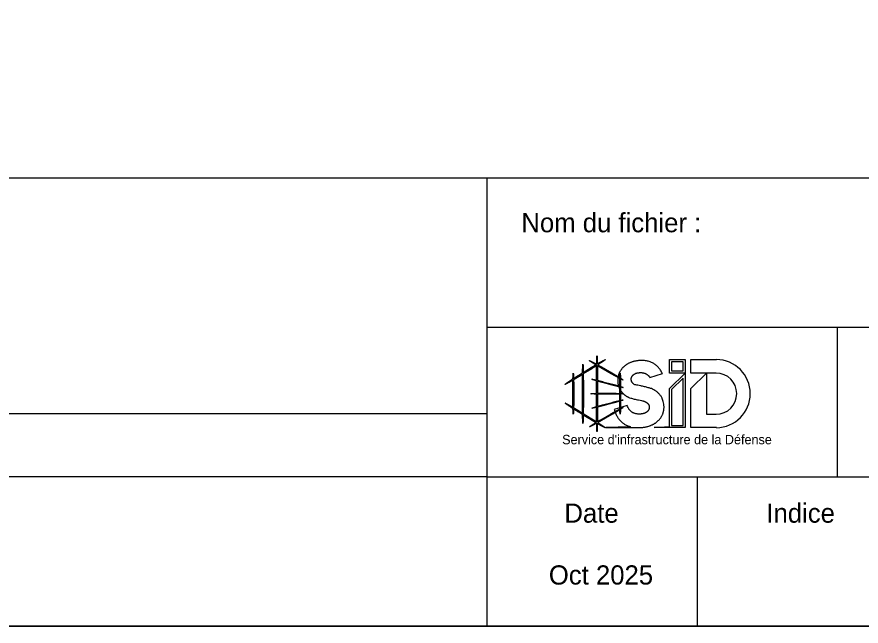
# Model space of a CAD drawing. Extents: x 37864 to 38032, y 453991 to 454052.
# Drawn here: x 37923.89 to 37937.08, y 453990.82 to 454000.33 of the extents above; entities that cross this region are included whole.
import ezdxf

# ---------------------------------------------------------------- set-up
doc = ezdxf.new("R2010")
doc.units = 0

msp = doc.modelspace()

# ---------------------------------------------------------------- linework, layer by layer
at = {"layer": 'DEFPOINTS'}
for p, q in [((37931.232, 453997.816), (37931.232, 453990.816)), ((37931.232, 453995.483), (37941.08, 453995.483)), ((37936.702, 453995.483), (37936.702, 453993.149)), ((37932.737, 453994.778), (37932.86, 453994.853)), ((37932.87, 453994.836), (37932.738, 453994.754)), ((37933.173, 453994.758), (37933.011, 453994.851)), ((37933.02, 453994.865), (37933.182, 453994.772)), ((37932.666, 453994.734), (37932.727, 453994.772)), ((37932.727, 453994.748), (37932.677, 453994.717)), ((37932.945, 453994.657), (37932.945, 453994.716)), ((37932.959, 453994.716), (37932.959, 453994.654)), ((37933.778, 453994.7), (37933.973, 453994.76)), ((37932.575, 453994.347), (37932.575, 453994.544)), ((37932.588, 453994.544), (37932.588, 453994.347)), ((37932.725, 453994.303), (37932.725, 453994.588)), ((37932.739, 453994.588), (37932.739, 453994.303)), ((37932.945, 453994.451), (37932.945, 453994.647)), ((37932.959, 453994.643), (37932.959, 453994.451)), ((37933.19, 453994.581), (37933.04, 453994.62)), ((37933.044, 453994.633), (37933.193, 453994.594)), ((37933.307, 453994.45), (37933.307, 453994.544)), ((37933.321, 453994.544), (37933.321, 453994.449)), ((37932.945, 453994.244), (37932.945, 453994.44)), ((37932.959, 453994.44), (37932.959, 453994.248)), ((37933.031, 453994.452), (37933.186, 453994.452)), ((37933.186, 453994.439), (37933.031, 453994.439)), ((37933.307, 453994.347), (37933.307, 453994.441)), ((37933.321, 453994.442), (37933.321, 453994.347)), ((37933.04, 453994.271), (37933.19, 453994.31)), ((37933.193, 453994.297), (37933.044, 453994.258)), ((37932.727, 453994.119), (37932.666, 453994.157)), ((37932.677, 453994.174), (37932.727, 453994.143)), ((37932.738, 453994.137), (37932.87, 453994.055)), ((37932.945, 453994.175), (37932.945, 453994.234)), ((37932.959, 453994.237), (37932.959, 453994.175)), ((37933.011, 453994.04), (37933.173, 453994.133)), ((37932.86, 453994.038), (37932.737, 453994.113)), ((37933.182, 453994.119), (37933.02, 453994.026)), ((37933.476, 453993.93), (37933.091, 453993.916)), ((37933.091, 453993.916), (37933.602, 453993.916)), ((37931.232, 453993.149), (37946.064, 453993.149)), ((37934.514, 453993.149), (37934.514, 453990.816))]:
    msp.add_line(p, q, dxfattribs=at)
for points in [[(37864.064, 453990.816), (37946.064, 453990.816), (37946.064, 454048.216), (37864.064, 454048.216)], [(37906.064, 453997.816), (37946.064, 453997.816), (37946.064, 453990.816), (37906.064, 453990.816)], [(37934.085, 453994.979), (37934.328, 453994.979), (37934.328, 453994.768), (37934.085, 453994.768)], [(37934.117, 453994.801), (37934.295, 453994.801), (37934.295, 453994.946), (37934.117, 453994.946)], [(37934.328, 453993.916), (37934.085, 453993.916), (37933.843, 453993.916), (37934.085, 453993.936), (37934.085, 453994.525), (37934.328, 453994.768)], [(37934.295, 453994.689), (37934.117, 453994.511), (37934.117, 453993.948), (37934.295, 453993.948)], [(37916.578, 453994.139), (37931.232, 453994.139), (37931.232, 453993.149), (37916.578, 453993.149)]]:
    msp.add_lwpolyline(points, close=True, dxfattribs=at)
for points in [[(37934.813, 453994.768), (37934.417, 453994.768), (37934.417, 453994.979), (37934.817, 453994.979)], [(37934.817, 453993.916), (37934.417, 453993.916), (37934.417, 453994.525), (37934.66, 453994.768), (37934.66, 453994.126), (37934.813, 453994.126)], [(37933.429, 453994.247), (37933.424, 453994.264), (37933.219, 453994.201)]]:
    msp.add_lwpolyline(points, dxfattribs=at)
for radius, start, end in [(0.532, 270.4248, 89.5752), (0.321, 270, 90)]:
    msp.add_arc((37934.813, 453994.447), radius, start, end, dxfattribs=at)
for points, degree in [([(37932.933, 453994.897), (37932.891, 453994.923), (37932.852, 453994.948), (37932.834, 453994.963)], 2), ([(37932.834, 453994.963), (37932.857, 453994.954), (37932.901, 453994.931), (37932.947, 453994.906)], 2), ([(37932.947, 453994.906), (37932.949, 453994.961), (37932.95, 453995.008), (37932.952, 453995.036)], 2), ([(37932.952, 453995.036), (37932.955, 453995.009), (37932.956, 453994.964), (37932.957, 453994.912)], 2), ([(37932.957, 453994.912), (37933.008, 453994.941), (37933.056, 453994.967), (37933.082, 453994.978)], 2), ([(37933.082, 453994.978), (37933.06, 453994.96), (37933.014, 453994.929), (37932.965, 453994.896)], 2), ([(37933.6, 453994.962), (37933.442, 453994.946), (37933.353, 453994.849)], 2), ([(37933.973, 453994.76), (37933.864, 453994.988), (37933.6, 453994.962)], 2), ([(37932.727, 453994.772), (37932.728, 453994.829), (37932.73, 453994.879), (37932.732, 453994.908)], 2), ([(37932.732, 453994.908), (37932.735, 453994.88), (37932.736, 453994.833), (37932.737, 453994.778)], 2), ([(37932.86, 453994.853), (37932.864, 453994.856), (37932.869, 453994.859), (37932.873, 453994.862)], 2), ([(37932.884, 453994.845), (37932.879, 453994.842), (37932.875, 453994.839), (37932.87, 453994.836)], 2), ([(37932.873, 453994.862), (37932.892, 453994.873), (37932.913, 453994.885), (37932.933, 453994.897)], 2), ([(37932.947, 453994.885), (37932.926, 453994.871), (37932.904, 453994.857), (37932.884, 453994.845)], 2), ([(37932.946, 453994.736), (37932.946, 453994.784), (37932.946, 453994.836), (37932.947, 453994.885)], 2), ([(37932.947, 453994.906), (37932.947, 453994.906), (37932.947, 453994.906), (37932.947, 453994.906)], 2), ([(37932.958, 453994.882), (37932.959, 453994.834), (37932.959, 453994.783), (37932.959, 453994.736)], 2), ([(37933, 453994.857), (37932.986, 453994.865), (37932.972, 453994.874), (37932.958, 453994.882)], 2), ([(37932.965, 453994.896), (37932.979, 453994.888), (37932.994, 453994.88), (37933.008, 453994.872)], 2), ([(37933.011, 453994.851), (37933.008, 453994.853), (37933.004, 453994.855), (37933, 453994.857)], 2), ([(37933.008, 453994.872), (37933.012, 453994.87), (37933.016, 453994.867), (37933.02, 453994.865)], 2), ([(37933.353, 453994.849), (37933.265, 453994.752), (37933.277, 453994.624)], 2), ([(37932.455, 453994.592), (37932.477, 453994.611), (37932.525, 453994.644), (37932.577, 453994.677)], 2), ([(37932.576, 453994.657), (37932.526, 453994.628), (37932.48, 453994.603), (37932.455, 453994.592)], 2), ([(37932.575, 453994.558), (37932.575, 453994.59), (37932.575, 453994.625), (37932.576, 453994.657)], 2), ([(37932.577, 453994.677), (37932.578, 453994.714), (37932.579, 453994.747), (37932.581, 453994.765)], 2), ([(37932.581, 453994.765), (37932.584, 453994.748), (37932.585, 453994.718), (37932.586, 453994.684)], 2), ([(37932.586, 453994.684), (37932.609, 453994.698), (37932.631, 453994.712), (37932.653, 453994.726)], 2), ([(37932.663, 453994.709), (37932.639, 453994.694), (37932.613, 453994.678), (37932.587, 453994.663)], 2), ([(37932.587, 453994.663), (37932.588, 453994.629), (37932.588, 453994.592), (37932.588, 453994.558)], 2), ([(37932.653, 453994.726), (37932.657, 453994.729), (37932.662, 453994.732), (37932.666, 453994.734)], 2), ([(37932.677, 453994.717), (37932.673, 453994.714), (37932.668, 453994.712), (37932.663, 453994.709)], 2), ([(37932.725, 453994.608), (37932.726, 453994.653), (37932.726, 453994.702), (37932.727, 453994.748)], 2), ([(37932.738, 453994.754), (37932.738, 453994.707), (37932.739, 453994.655), (37932.739, 453994.608)], 2), ([(37932.945, 453994.647), (37932.915, 453994.656), (37932.889, 453994.664), (37932.874, 453994.671)], 2), ([(37932.874, 453994.671), (37932.889, 453994.669), (37932.916, 453994.664), (37932.945, 453994.657)], 2), ([(37932.945, 453994.716), (37932.945, 453994.722), (37932.946, 453994.729), (37932.946, 453994.736)], 2), ([(37932.959, 453994.736), (37932.959, 453994.729), (37932.959, 453994.722), (37932.959, 453994.716)], 2), ([(37932.959, 453994.654), (37932.984, 453994.648), (37933.01, 453994.642), (37933.033, 453994.636)], 2), ([(37933.185, 453994.751), (37933.181, 453994.753), (37933.177, 453994.756), (37933.173, 453994.758)], 2), ([(37933.182, 453994.772), (37933.185, 453994.77), (37933.189, 453994.768), (37933.193, 453994.766)], 2), ([(37933.309, 453994.684), (37933.272, 453994.703), (37933.225, 453994.728), (37933.185, 453994.751)], 2), ([(37933.193, 453994.766), (37933.232, 453994.743), (37933.275, 453994.717), (37933.309, 453994.695)], 2), ([(37933.307, 453994.562), (37933.307, 453994.602), (37933.308, 453994.646), (37933.309, 453994.684)], 2), ([(37933.309, 453994.695), (37933.31, 453994.724), (37933.312, 453994.75), (37933.314, 453994.765)], 2), ([(37933.314, 453994.765), (37933.316, 453994.749), (37933.317, 453994.721), (37933.318, 453994.689)], 2), ([(37933.318, 453994.689), (37933.336, 453994.678), (37933.35, 453994.668), (37933.359, 453994.66)], 2), ([(37933.359, 453994.66), (37933.349, 453994.664), (37933.335, 453994.671), (37933.319, 453994.679)], 2), ([(37933.319, 453994.679), (37933.32, 453994.641), (37933.32, 453994.597), (37933.321, 453994.558)], 2), ([(37933.487, 453994.662), (37933.483, 453994.702), (37933.514, 453994.735)], 2), ([(37933.535, 453994.59), (37933.492, 453994.619), (37933.487, 453994.662)], 2), ([(37933.514, 453994.735), (37933.545, 453994.769), (37933.609, 453994.774)], 2), ([(37933.609, 453994.774), (37933.68, 453994.78), (37933.724, 453994.753)], 2), ([(37933.724, 453994.753), (37933.752, 453994.736), (37933.778, 453994.7)], 2), ([(37932.575, 453994.544), (37932.575, 453994.549), (37932.575, 453994.553), (37932.575, 453994.558)], 2), ([(37932.588, 453994.558), (37932.588, 453994.553), (37932.588, 453994.549), (37932.588, 453994.544)], 2), ([(37932.725, 453994.588), (37932.725, 453994.595), (37932.725, 453994.601), (37932.725, 453994.608)], 2), ([(37932.739, 453994.608), (37932.739, 453994.601), (37932.739, 453994.595), (37932.739, 453994.588)], 2), ([(37933.03, 453994.623), (37933.007, 453994.629), (37932.983, 453994.636), (37932.959, 453994.643)], 2), ([(37933.04, 453994.62), (37933.037, 453994.621), (37933.033, 453994.622), (37933.03, 453994.623)], 2), ([(37933.033, 453994.636), (37933.037, 453994.635), (37933.04, 453994.634), (37933.044, 453994.633)], 2), ([(37933.2, 453994.578), (37933.197, 453994.579), (37933.193, 453994.58), (37933.19, 453994.581)], 2), ([(37933.193, 453994.594), (37933.197, 453994.593), (37933.2, 453994.592), (37933.204, 453994.591)], 2), ([(37933.307, 453994.553), (37933.274, 453994.56), (37933.235, 453994.569), (37933.2, 453994.578)], 2), ([(37933.204, 453994.591), (37933.238, 453994.582), (37933.276, 453994.571), (37933.307, 453994.562)], 2), ([(37933.277, 453994.624), (37933.285, 453994.539), (37933.335, 453994.477)], 2), ([(37933.307, 453994.544), (37933.307, 453994.547), (37933.307, 453994.55), (37933.307, 453994.553)], 2), ([(37933.321, 453994.558), (37933.321, 453994.558), (37933.321, 453994.558), (37933.321, 453994.557)], 2), ([(37933.321, 453994.557), (37933.337, 453994.552), (37933.35, 453994.547), (37933.359, 453994.544)], 2), ([(37933.359, 453994.544), (37933.35, 453994.544), (37933.337, 453994.547), (37933.321, 453994.55)], 2), ([(37933.321, 453994.55), (37933.321, 453994.548), (37933.321, 453994.546), (37933.321, 453994.544)], 2), ([(37933.998, 453994.256), (37933.996, 453994.29), (37933.98, 453994.351), (37933.964, 453994.388), (37933.94, 453994.424), (37933.905, 453994.46), (37933.875, 453994.486), (37933.84, 453994.507), (37933.803, 453994.525), (37933.754, 453994.54), (37933.692, 453994.555), (37933.633, 453994.569), (37933.593, 453994.576), (37933.545, 453994.585), (37933.535, 453994.59)], 3), ([(37932.858, 453994.446), (37932.875, 453994.448), (37932.909, 453994.45), (37932.945, 453994.451)], 2), ([(37932.945, 453994.44), (37932.909, 453994.441), (37932.875, 453994.443), (37932.858, 453994.446)], 2), ([(37932.959, 453994.451), (37932.98, 453994.452), (37933.001, 453994.452), (37933.02, 453994.452)], 2), ([(37933.02, 453994.439), (37933.001, 453994.439), (37932.98, 453994.439), (37932.959, 453994.44)], 2), ([(37933.02, 453994.452), (37933.024, 453994.452), (37933.028, 453994.452), (37933.031, 453994.452)], 2), ([(37933.031, 453994.439), (37933.028, 453994.439), (37933.024, 453994.439), (37933.02, 453994.439)], 2), ([(37933.186, 453994.452), (37933.189, 453994.452), (37933.193, 453994.452), (37933.197, 453994.452)], 2), ([(37933.197, 453994.439), (37933.193, 453994.439), (37933.189, 453994.439), (37933.186, 453994.439)], 2), ([(37933.197, 453994.452), (37933.233, 453994.452), (37933.274, 453994.451), (37933.307, 453994.45)], 2), ([(37933.307, 453994.441), (37933.274, 453994.44), (37933.233, 453994.439), (37933.197, 453994.439)], 2), ([(37933.321, 453994.449), (37933.337, 453994.448), (37933.35, 453994.447), (37933.359, 453994.446)], 2), ([(37933.359, 453994.446), (37933.35, 453994.444), (37933.337, 453994.443), (37933.321, 453994.442)], 2), ([(37933.335, 453994.477), (37933.385, 453994.416), (37933.448, 453994.388)], 2), ([(37933.448, 453994.388), (37933.456, 453994.385), (37933.477, 453994.378), (37933.531, 453994.362), (37933.596, 453994.35), (37933.665, 453994.336), (37933.672, 453994.333)], 3), ([(37932.577, 453994.214), (37932.525, 453994.247), (37932.477, 453994.28), (37932.455, 453994.299)], 2), ([(37932.455, 453994.299), (37932.48, 453994.288), (37932.526, 453994.263), (37932.576, 453994.234)], 2), ([(37932.575, 453994.333), (37932.575, 453994.338), (37932.575, 453994.342), (37932.575, 453994.347)], 2), ([(37932.576, 453994.234), (37932.575, 453994.266), (37932.575, 453994.301), (37932.575, 453994.333)], 2), ([(37932.588, 453994.333), (37932.588, 453994.299), (37932.588, 453994.262), (37932.587, 453994.228)], 2), ([(37932.588, 453994.347), (37932.588, 453994.342), (37932.588, 453994.338), (37932.588, 453994.333)], 2), ([(37932.725, 453994.283), (37932.725, 453994.29), (37932.725, 453994.296), (37932.725, 453994.303)], 2), ([(37932.727, 453994.143), (37932.726, 453994.189), (37932.726, 453994.238), (37932.725, 453994.283)], 2), ([(37932.739, 453994.283), (37932.739, 453994.236), (37932.738, 453994.184), (37932.738, 453994.137)], 2), ([(37932.739, 453994.303), (37932.739, 453994.296), (37932.739, 453994.29), (37932.739, 453994.283)], 2), ([(37932.959, 453994.248), (37932.983, 453994.255), (37933.007, 453994.262), (37933.03, 453994.268)], 2), ([(37933.03, 453994.268), (37933.033, 453994.269), (37933.037, 453994.27), (37933.04, 453994.271)], 2), ([(37933.044, 453994.258), (37933.04, 453994.257), (37933.037, 453994.256), (37933.033, 453994.255)], 2), ([(37933.19, 453994.31), (37933.193, 453994.311), (37933.197, 453994.312), (37933.2, 453994.313)], 2), ([(37933.204, 453994.3), (37933.2, 453994.299), (37933.197, 453994.298), (37933.193, 453994.297)], 2), ([(37933.2, 453994.313), (37933.235, 453994.322), (37933.274, 453994.331), (37933.307, 453994.338)], 2), ([(37933.307, 453994.329), (37933.276, 453994.32), (37933.238, 453994.309), (37933.204, 453994.3)], 2), ([(37933.307, 453994.338), (37933.307, 453994.341), (37933.307, 453994.344), (37933.307, 453994.347)], 2), ([(37933.309, 453994.207), (37933.308, 453994.245), (37933.307, 453994.289), (37933.307, 453994.329)], 2), ([(37933.321, 453994.333), (37933.32, 453994.294), (37933.32, 453994.25), (37933.319, 453994.212)], 2), ([(37933.321, 453994.347), (37933.321, 453994.345), (37933.321, 453994.343), (37933.321, 453994.341)], 2), ([(37933.321, 453994.341), (37933.337, 453994.344), (37933.35, 453994.347), (37933.359, 453994.347)], 2), ([(37933.359, 453994.347), (37933.35, 453994.344), (37933.337, 453994.339), (37933.321, 453994.334)], 2), ([(37933.321, 453994.334), (37933.321, 453994.333), (37933.321, 453994.333), (37933.321, 453994.333)], 2), ([(37933.672, 453994.333), (37933.721, 453994.316), (37933.738, 453994.3)], 2), ([(37933.738, 453994.3), (37933.766, 453994.273), (37933.768, 453994.24)], 2), ([(37932.581, 453994.126), (37932.579, 453994.144), (37932.578, 453994.177), (37932.577, 453994.214)], 2), ([(37932.586, 453994.207), (37932.585, 453994.173), (37932.584, 453994.143), (37932.581, 453994.126)], 2), ([(37932.653, 453994.165), (37932.631, 453994.179), (37932.609, 453994.193), (37932.586, 453994.207)], 2), ([(37932.587, 453994.228), (37932.613, 453994.213), (37932.639, 453994.197), (37932.663, 453994.182)], 2), ([(37932.666, 453994.157), (37932.662, 453994.159), (37932.657, 453994.162), (37932.653, 453994.165)], 2), ([(37932.663, 453994.182), (37932.668, 453994.179), (37932.673, 453994.177), (37932.677, 453994.174)], 2), ([(37932.874, 453994.22), (37932.889, 453994.227), (37932.915, 453994.235), (37932.945, 453994.244)], 2), ([(37932.945, 453994.234), (37932.916, 453994.227), (37932.889, 453994.222), (37932.874, 453994.22)], 2), ([(37932.946, 453994.155), (37932.946, 453994.162), (37932.945, 453994.169), (37932.945, 453994.175)], 2), ([(37932.947, 453994.006), (37932.946, 453994.055), (37932.946, 453994.107), (37932.946, 453994.155)], 2), ([(37932.959, 453994.155), (37932.959, 453994.108), (37932.959, 453994.057), (37932.958, 453994.009)], 2), ([(37933.033, 453994.255), (37933.01, 453994.249), (37932.984, 453994.243), (37932.959, 453994.237)], 2), ([(37932.959, 453994.175), (37932.959, 453994.169), (37932.959, 453994.162), (37932.959, 453994.155)], 2), ([(37933.173, 453994.133), (37933.177, 453994.135), (37933.181, 453994.138), (37933.185, 453994.14)], 2), ([(37933.193, 453994.125), (37933.189, 453994.123), (37933.185, 453994.121), (37933.182, 453994.119)], 2), ([(37933.185, 453994.14), (37933.225, 453994.163), (37933.272, 453994.188), (37933.309, 453994.207)], 2), ([(37933.309, 453994.196), (37933.275, 453994.174), (37933.232, 453994.148), (37933.193, 453994.125)], 2), ([(37933.219, 453994.201), (37933.288, 453993.98), (37933.476, 453993.93)], 2), ([(37933.314, 453994.126), (37933.312, 453994.141), (37933.31, 453994.167), (37933.309, 453994.196)], 2), ([(37933.318, 453994.202), (37933.317, 453994.17), (37933.316, 453994.142), (37933.314, 453994.126)], 2), ([(37933.359, 453994.231), (37933.35, 453994.223), (37933.336, 453994.213), (37933.318, 453994.202)], 2), ([(37933.319, 453994.212), (37933.335, 453994.22), (37933.349, 453994.227), (37933.359, 453994.231)], 2), ([(37933.624, 453994.128), (37933.48, 453994.121), (37933.429, 453994.247)], 2), ([(37933.735, 453994.164), (37933.699, 453994.132), (37933.624, 453994.128)], 2), ([(37933.768, 453994.24), (37933.771, 453994.196), (37933.735, 453994.164)], 2), ([(37933.909, 453994.026), (37934.006, 453994.124), (37933.998, 453994.256)], 2), ([(37932.732, 453993.983), (37932.73, 453994.012), (37932.728, 453994.062), (37932.727, 453994.119)], 2), ([(37932.737, 453994.113), (37932.736, 453994.058), (37932.735, 453994.011), (37932.732, 453993.983)], 2), ([(37932.834, 453993.928), (37932.852, 453993.943), (37932.891, 453993.968), (37932.933, 453993.994)], 2), ([(37932.873, 453994.029), (37932.869, 453994.032), (37932.864, 453994.035), (37932.86, 453994.038)], 2), ([(37932.87, 453994.055), (37932.875, 453994.052), (37932.879, 453994.049), (37932.884, 453994.046)], 2), ([(37932.933, 453993.994), (37932.913, 453994.006), (37932.892, 453994.018), (37932.873, 453994.029)], 2), ([(37932.884, 453994.046), (37932.904, 453994.034), (37932.926, 453994.02), (37932.947, 453994.006)], 2), ([(37932.958, 453994.009), (37932.972, 453994.017), (37932.986, 453994.026), (37933, 453994.034)], 2), ([(37933.008, 453994.019), (37932.994, 453994.011), (37932.979, 453994.003), (37932.965, 453993.995)], 2), ([(37932.965, 453993.995), (37933.014, 453993.962), (37933.06, 453993.931), (37933.082, 453993.913)], 2), ([(37933, 453994.034), (37933.004, 453994.036), (37933.008, 453994.038), (37933.011, 453994.04)], 2), ([(37933.02, 453994.026), (37933.016, 453994.024), (37933.012, 453994.021), (37933.008, 453994.019)], 2), ([(37933.629, 453993.917), (37933.812, 453993.927), (37933.909, 453994.026)], 2), ([(37932.947, 453993.985), (37932.901, 453993.96), (37932.857, 453993.937), (37932.834, 453993.928)], 2), ([(37932.952, 453993.855), (37932.95, 453993.883), (37932.949, 453993.93), (37932.947, 453993.985)], 2), ([(37932.947, 453993.985), (37932.947, 453993.985), (37932.947, 453993.985), (37932.947, 453993.985)], 2), ([(37932.957, 453993.979), (37932.956, 453993.927), (37932.955, 453993.882), (37932.952, 453993.855)], 2), ([(37933.082, 453993.913), (37933.056, 453993.924), (37933.008, 453993.95), (37932.957, 453993.979)], 2), ([(37933.602, 453993.916), (37933.615, 453993.916), (37933.629, 453993.917)], 2)]:
    msp.add_open_spline(points, degree=degree, dxfattribs=at)

# ---------------------------------------------------------------- texts
for s, height, p in [('Nom du fichier :', 0.3, (37931.771, 453996.967)), ("Service d'infrastructure de la Défense", 0.14709, (37932.408, 453993.656)), ('DUBOIS SANDRINE', 0.0002, (37931.229, 453993.149)), ('DUBOIS SANDRINE', 0.0002, (37931.229, 453993.149)), ('Date', 0.3, (37932.443, 453992.431)), ('Indice', 0.3, (37935.597, 453992.431)), ('Oct 2025', 0.3, (37932.2, 453991.465))]:
    msp.add_text(s, height=height, rotation=360, dxfattribs=at).set_placement(p)

doc.saveas('drawing.dxf')
